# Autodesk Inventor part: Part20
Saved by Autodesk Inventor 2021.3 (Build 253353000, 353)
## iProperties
Created: 2022-08
Part Number: Part20
Material: Generic
Document SubType Name: Modeling
Designer: Administrator
Density: 1 g/cm^3
Appearance: Default
Author: Administrator
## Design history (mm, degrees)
feature "Body1"
body "Solid1"
